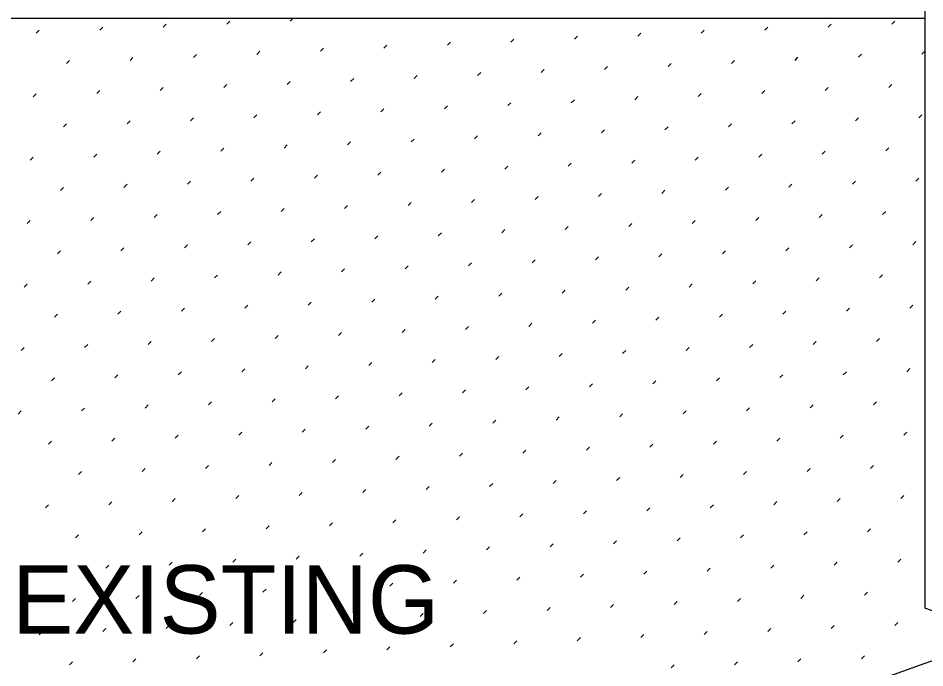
# Model space of a CAD drawing. Extents: x 49991.4 to 50021, y 49987.6 to 50011.4.
# Drawn here: x 50014.07 to 50015.13, y 49997.03 to 49997.79 of the extents above; entities that cross this region are included whole.
import ezdxf

# ---------------------------------------------------------------- set-up
doc = ezdxf.new("R2010")
doc.units = 0
for name, color, linetype in [('Level 1', 7, 'Continuous'), ('Level 10', 7, 'Continuous'), ('Level 2', 7, 'Continuous'), ('Level 6', 7, 'Continuous')]:
    doc.layers.add(name, color=color, linetype=linetype)

msp = doc.modelspace()

# ---------------------------------------------------------------- linework, layer by layer
at = {"layer": 'Level 1'}
msp.add_line((50011.6848, 49997.7903), (50015.1301, 49997.7903), dxfattribs=at)
at = {"layer": 'Level 10'}
for p, q in [((50014.2393, 49997.7797), (50014.2428, 49997.7833)), ((50014.3136, 49997.7833), (50014.3171, 49997.7868)), ((50014.3878, 49997.7868), (50014.3913, 49997.7904)), ((50015.0172, 49997.7798), (50015.0207, 49997.7834)), ((50015.0914, 49997.7834), (50015.095, 49997.7869)), ((50014.0908, 49997.7727), (50014.0943, 49997.7762)), ((50014.165, 49997.7762), (50014.1686, 49997.7797)), ((50014.7944, 49997.7692), (50014.798, 49997.7727)), ((50014.8687, 49997.7727), (50014.8722, 49997.7763)), ((50014.9429, 49997.7763), (50014.9465, 49997.7798)), ((50014.5717, 49997.7586), (50014.5752, 49997.7621)), ((50014.6459, 49997.7621), (50014.6495, 49997.7656)), ((50014.7202, 49997.7656), (50014.7237, 49997.7692)), ((50014.3489, 49997.7479), (50014.3524, 49997.7515)), ((50014.4232, 49997.7515), (50014.4267, 49997.755)), ((50014.4974, 49997.755), (50014.501, 49997.7586)), ((50015.1268, 49997.748), (50015.1303, 49997.7515)), ((50014.1262, 49997.7373), (50014.1297, 49997.7408)), ((50014.2004, 49997.7409), (50014.2039, 49997.7444)), ((50014.2747, 49997.7444), (50014.2782, 49997.7479)), ((50014.904, 49997.7374), (50014.9076, 49997.7409)), ((50014.9783, 49997.7409), (50014.9818, 49997.7445)), ((50015.0525, 49997.7445), (50015.0561, 49997.748)), ((50014.6813, 49997.7268), (50014.6848, 49997.7303)), ((50014.7555, 49997.7303), (50014.7591, 49997.7338)), ((50014.8298, 49997.7338), (50014.8333, 49997.7374)), ((50014.4585, 49997.7161), (50014.4621, 49997.7197)), ((50014.5328, 49997.7197), (50014.5363, 49997.7232)), ((50014.607, 49997.7232), (50014.6106, 49997.7267)), ((50014.2358, 49997.7055), (50014.2393, 49997.709)), ((50014.31, 49997.709), (50014.3135, 49997.7126)), ((50014.3843, 49997.7126), (50014.3878, 49997.7161)), ((50015.0136, 49997.7056), (50015.0172, 49997.7091)), ((50015.0879, 49997.7091), (50015.0914, 49997.7126)), ((50014.0873, 49997.6984), (50014.0908, 49997.7019)), ((50014.1615, 49997.702), (50014.165, 49997.7055)), ((50014.7909, 49997.6949), (50014.7944, 49997.6985)), ((50014.8651, 49997.6985), (50014.8687, 49997.702)), ((50014.9394, 49997.702), (50014.9429, 49997.7056)), ((50014.5681, 49997.6843), (50014.5717, 49997.6878)), ((50014.6424, 49997.6879), (50014.6459, 49997.6914)), ((50014.7166, 49997.6914), (50014.7202, 49997.6949)), ((50014.3454, 49997.6737), (50014.3489, 49997.6772)), ((50014.4196, 49997.6772), (50014.4232, 49997.6808)), ((50014.4939, 49997.6808), (50014.4974, 49997.6843)), ((50015.1233, 49997.6738), (50015.1268, 49997.6773)), ((50014.1226, 49997.6631), (50014.1261, 49997.6666)), ((50014.1969, 49997.6666), (50014.2004, 49997.6701)), ((50014.2711, 49997.6701), (50014.2747, 49997.6737)), ((50014.9005, 49997.6631), (50014.904, 49997.6667)), ((50014.9747, 49997.6667), (50014.9783, 49997.6702)), ((50015.049, 49997.6702), (50015.0525, 49997.6737)), ((50014.6777, 49997.6525), (50014.6813, 49997.656)), ((50014.752, 49997.656), (50014.7555, 49997.6596)), ((50014.8262, 49997.6596), (50014.8298, 49997.6631)), ((50014.455, 49997.6419), (50014.4585, 49997.6454)), ((50014.5292, 49997.6454), (50014.5328, 49997.6489)), ((50014.6035, 49997.649), (50014.607, 49997.6525)), ((50014.2322, 49997.6312), (50014.2358, 49997.6348)), ((50014.3065, 49997.6348), (50014.31, 49997.6383)), ((50014.3807, 49997.6383), (50014.3843, 49997.6419)), ((50015.0101, 49997.6313), (50015.0136, 49997.6348)), ((50015.0844, 49997.6349), (50015.0879, 49997.6384)), ((50014.0837, 49997.6242), (50014.0872, 49997.6277)), ((50014.158, 49997.6277), (50014.1615, 49997.6312)), ((50014.7873, 49997.6207), (50014.7909, 49997.6242)), ((50014.8616, 49997.6242), (50014.8651, 49997.6278)), ((50014.9359, 49997.6278), (50014.9394, 49997.6313)), ((50014.5646, 49997.6101), (50014.5681, 49997.6136)), ((50014.6388, 49997.6136), (50014.6424, 49997.6171)), ((50014.7131, 49997.6171), (50014.7166, 49997.6207)), ((50014.3418, 49997.5994), (50014.3454, 49997.603)), ((50014.4161, 49997.603), (50014.4196, 49997.6065)), ((50014.4903, 49997.6065), (50014.4939, 49997.6101)), ((50015.1197, 49997.5995), (50015.1232, 49997.603)), ((50014.1191, 49997.5888), (50014.1226, 49997.5923)), ((50014.1933, 49997.5923), (50014.1969, 49997.5959)), ((50014.2676, 49997.5959), (50014.2711, 49997.5994)), ((50014.897, 49997.5889), (50014.9005, 49997.5924)), ((50014.9712, 49997.5924), (50014.9747, 49997.596)), ((50015.0455, 49997.596), (50015.049, 49997.5995)), ((50014.6742, 49997.5782), (50014.6777, 49997.5818)), ((50014.7484, 49997.5818), (50014.752, 49997.5853)), ((50014.8227, 49997.5853), (50014.8262, 49997.5889)), ((50014.4514, 49997.5676), (50014.455, 49997.5712)), ((50014.5257, 49997.5712), (50014.5292, 49997.5747)), ((50014.5999, 49997.5747), (50014.6035, 49997.5782)), ((50014.2287, 49997.557), (50014.2322, 49997.5605)), ((50014.3029, 49997.5605), (50014.3065, 49997.5641)), ((50014.3772, 49997.5641), (50014.3807, 49997.5676)), ((50015.0066, 49997.5571), (50015.0101, 49997.5606)), ((50015.0808, 49997.5606), (50015.0844, 49997.5641)), ((50014.0802, 49997.5499), (50014.0837, 49997.5534)), ((50014.1544, 49997.5534), (50014.158, 49997.557)), ((50014.7838, 49997.5464), (50014.7873, 49997.55)), ((50014.8581, 49997.55), (50014.8616, 49997.5535)), ((50014.9323, 49997.5535), (50014.9358, 49997.5571)), ((50014.561, 49997.5358), (50014.5646, 49997.5393)), ((50014.6353, 49997.5393), (50014.6388, 49997.5429)), ((50014.7095, 49997.5429), (50014.7131, 49997.5464)), ((50014.3383, 49997.5252), (50014.3418, 49997.5287)), ((50014.4125, 49997.5287), (50014.4161, 49997.5323)), ((50014.4868, 49997.5323), (50014.4903, 49997.5358)), ((50015.1162, 49997.5252), (50015.1197, 49997.5288)), ((50014.1155, 49997.5145), (50014.1191, 49997.5181)), ((50014.1898, 49997.5181), (50014.1933, 49997.5216)), ((50014.264, 49997.5216), (50014.2676, 49997.5252)), ((50014.8934, 49997.5146), (50014.8969, 49997.5182)), ((50014.9677, 49997.5182), (50014.9712, 49997.5217)), ((50015.0419, 49997.5217), (50015.0455, 49997.5252)), ((50014.6707, 49997.504), (50014.6742, 49997.5075)), ((50014.7449, 49997.5075), (50014.7484, 49997.5111)), ((50014.8192, 49997.5111), (50014.8227, 49997.5146)), ((50014.4479, 49997.4934), (50014.4514, 49997.4969)), ((50014.5221, 49997.4969), (50014.5257, 49997.5004)), ((50014.5964, 49997.5004), (50014.5999, 49997.504)), ((50014.2251, 49997.4827), (50014.2287, 49997.4863)), ((50014.2994, 49997.4863), (50014.3029, 49997.4898)), ((50014.3736, 49997.4898), (50014.3772, 49997.4934)), ((50015.003, 49997.4828), (50015.0066, 49997.4863)), ((50015.0773, 49997.4863), (50015.0808, 49997.4899)), ((50014.0766, 49997.4757), (50014.0802, 49997.4792)), ((50014.1509, 49997.4792), (50014.1544, 49997.4827)), ((50014.7803, 49997.4722), (50014.7838, 49997.4757)), ((50014.8545, 49997.4757), (50014.858, 49997.4793)), ((50014.9288, 49997.4793), (50014.9323, 49997.4828)), ((50014.5575, 49997.4616), (50014.561, 49997.4651)), ((50014.6318, 49997.4651), (50014.6353, 49997.4686)), ((50014.706, 49997.4686), (50014.7095, 49997.4722)), ((50014.3347, 49997.4509), (50014.3383, 49997.4545)), ((50014.409, 49997.4545), (50014.4125, 49997.458)), ((50014.4832, 49997.458), (50014.4868, 49997.4615)), ((50015.1126, 49997.451), (50015.1162, 49997.4545)), ((50014.112, 49997.4403), (50014.1155, 49997.4438)), ((50014.1862, 49997.4438), (50014.1898, 49997.4474)), ((50014.2605, 49997.4474), (50014.264, 49997.4509)), ((50014.8899, 49997.4404), (50014.8934, 49997.4439)), ((50014.9641, 49997.4439), (50014.9677, 49997.4474)), ((50015.0384, 49997.4475), (50015.0419, 49997.451)), ((50014.6671, 49997.4297), (50014.6706, 49997.4333)), ((50014.7414, 49997.4333), (50014.7449, 49997.4368)), ((50014.8156, 49997.4368), (50014.8192, 49997.4404)), ((50014.4443, 49997.4191), (50014.4479, 49997.4226)), ((50014.5186, 49997.4227), (50014.5221, 49997.4262)), ((50014.5929, 49997.4262), (50014.5964, 49997.4297)), ((50014.2216, 49997.4085), (50014.2251, 49997.412)), ((50014.2958, 49997.412), (50014.2994, 49997.4156)), ((50014.3701, 49997.4156), (50014.3736, 49997.4191)), ((50014.9995, 49997.4086), (50015.003, 49997.4121)), ((50015.0737, 49997.4121), (50015.0773, 49997.4156)), ((50014.0731, 49997.4014), (50014.0766, 49997.4049)), ((50014.1473, 49997.4049), (50014.1509, 49997.4085)), ((50014.7767, 49997.3979), (50014.7803, 49997.4015)), ((50014.851, 49997.4015), (50014.8545, 49997.405)), ((50014.9252, 49997.405), (50014.9288, 49997.4085)), ((50014.554, 49997.3873), (50014.5575, 49997.3908)), ((50014.6282, 49997.3908), (50014.6317, 49997.3944)), ((50014.7025, 49997.3944), (50014.706, 49997.3979)), ((50014.3312, 49997.3767), (50014.3347, 49997.3802)), ((50014.4055, 49997.3802), (50014.409, 49997.3837)), ((50014.4797, 49997.3838), (50014.4832, 49997.3873)), ((50015.1091, 49997.3767), (50015.1126, 49997.3803)), ((50014.1084, 49997.366), (50014.112, 49997.3696)), ((50014.1827, 49997.3696), (50014.1862, 49997.3731)), ((50014.2569, 49997.3731), (50014.2605, 49997.3767)), ((50014.8863, 49997.3661), (50014.8899, 49997.3696)), ((50014.9606, 49997.3697), (50014.9641, 49997.3732)), ((50015.0348, 49997.3732), (50015.0384, 49997.3767)), ((50014.6636, 49997.3555), (50014.6671, 49997.359)), ((50014.7378, 49997.359), (50014.7414, 49997.3626)), ((50014.8121, 49997.3626), (50014.8156, 49997.3661)), ((50014.4408, 49997.3449), (50014.4443, 49997.3484)), ((50014.5151, 49997.3484), (50014.5186, 49997.3519)), ((50014.5893, 49997.3519), (50014.5928, 49997.3555)), ((50014.218, 49997.3342), (50014.2216, 49997.3378)), ((50014.2923, 49997.3378), (50014.2958, 49997.3413)), ((50014.3666, 49997.3413), (50014.3701, 49997.3449)), ((50014.9959, 49997.3343), (50014.9995, 49997.3378)), ((50015.0702, 49997.3378), (50015.0737, 49997.3414)), ((50014.0695, 49997.3271), (50014.0731, 49997.3307)), ((50014.1438, 49997.3307), (50014.1473, 49997.3342)), ((50014.7732, 49997.3237), (50014.7767, 49997.3272)), ((50014.8474, 49997.3272), (50014.851, 49997.3308)), ((50014.9217, 49997.3308), (50014.9252, 49997.3343)), ((50014.5504, 49997.313), (50014.554, 49997.3166)), ((50014.6247, 49997.3166), (50014.6282, 49997.3201)), ((50014.6989, 49997.3201), (50014.7025, 49997.3237)), ((50014.3277, 49997.3024), (50014.3312, 49997.306)), ((50014.4019, 49997.306), (50014.4054, 49997.3095)), ((50014.4762, 49997.3095), (50014.4797, 49997.313)), ((50015.1055, 49997.3025), (50015.1091, 49997.306)), ((50014.1049, 49997.2918), (50014.1084, 49997.2953)), ((50014.1791, 49997.2953), (50014.1827, 49997.2989)), ((50014.2534, 49997.2989), (50014.2569, 49997.3024)), ((50014.8828, 49997.2919), (50014.8863, 49997.2954)), ((50014.957, 49997.2954), (50014.9606, 49997.2989)), ((50015.0313, 49997.2989), (50015.0348, 49997.3025)), ((50014.66, 49997.2812), (50014.6636, 49997.2848)), ((50014.7343, 49997.2848), (50014.7378, 49997.2883)), ((50014.8085, 49997.2883), (50014.8121, 49997.2919)), ((50014.4373, 49997.2706), (50014.4408, 49997.2741)), ((50014.5115, 49997.2741), (50014.5151, 49997.2777)), ((50014.5858, 49997.2777), (50014.5893, 49997.2812)), ((50014.2145, 49997.26), (50014.218, 49997.2635)), ((50014.2888, 49997.2635), (50014.2923, 49997.2671)), ((50014.363, 49997.2671), (50014.3665, 49997.2706)), ((50014.9924, 49997.26), (50014.9959, 49997.2636)), ((50015.0666, 49997.2636), (50015.0702, 49997.2671)), ((50014.1403, 49997.2564), (50014.1438, 49997.26)), ((50014.7696, 49997.2494), (50014.7732, 49997.253)), ((50014.8439, 49997.253), (50014.8474, 49997.2565)), ((50014.9181, 49997.2565), (50014.9217, 49997.26)), ((50014.5469, 49997.2388), (50014.5504, 49997.2423)), ((50014.6211, 49997.2423), (50014.6247, 49997.2459)), ((50014.6954, 49997.2459), (50014.6989, 49997.2494)), ((50014.3241, 49997.2282), (50014.3276, 49997.2317)), ((50014.3984, 49997.2317), (50014.4019, 49997.2352)), ((50014.4726, 49997.2352), (50014.4762, 49997.2388)), ((50015.102, 49997.2282), (50015.1055, 49997.2318)), ((50014.1014, 49997.2175), (50014.1049, 49997.2211)), ((50014.1756, 49997.2211), (50014.1791, 49997.2246)), ((50014.2499, 49997.2246), (50014.2534, 49997.2282)), ((50014.8792, 49997.2176), (50014.8828, 49997.2211)), ((50014.9535, 49997.2211), (50014.957, 49997.2247)), ((50015.0277, 49997.2247), (50015.0313, 49997.2282)), ((50014.6565, 49997.207), (50014.66, 49997.2105)), ((50014.7307, 49997.2105), (50014.7343, 49997.2141)), ((50014.805, 49997.2141), (50014.8085, 49997.2176)), ((50014.4337, 49997.1964), (50014.4373, 49997.1999)), ((50014.508, 49997.1999), (50014.5115, 49997.2034)), ((50014.5822, 49997.2034), (50014.5858, 49997.207)), ((50014.211, 49997.1857), (50014.2145, 49997.1893)), ((50014.2852, 49997.1893), (50014.2888, 49997.1928)), ((50014.3595, 49997.1928), (50014.363, 49997.1963)), ((50014.9888, 49997.1858), (50014.9924, 49997.1893)), ((50015.0631, 49997.1893), (50015.0666, 49997.1929)), ((50014.1367, 49997.1822), (50014.1402, 49997.1857)), ((50014.7661, 49997.1752), (50014.7696, 49997.1787)), ((50014.8403, 49997.1787), (50014.8439, 49997.1822)), ((50014.9146, 49997.1823), (50014.9181, 49997.1858)), ((50014.5433, 49997.1645), (50014.5469, 49997.1681)), ((50014.6176, 49997.1681), (50014.6211, 49997.1716)), ((50014.6918, 49997.1716), (50014.6954, 49997.1752)), ((50014.3206, 49997.1539), (50014.3241, 49997.1574)), ((50014.3948, 49997.1575), (50014.3984, 49997.161)), ((50014.4691, 49997.161), (50014.4726, 49997.1645)), ((50015.0985, 49997.154), (50015.102, 49997.1575)), ((50014.0978, 49997.1433), (50014.1013, 49997.1468)), ((50014.1721, 49997.1468), (50014.1756, 49997.1504)), ((50014.2463, 49997.1504), (50014.2499, 49997.1539)), ((50014.8757, 49997.1434), (50014.8792, 49997.1469)), ((50014.95, 49997.1469), (50014.9535, 49997.1504)), ((50015.0242, 49997.1504), (50015.0277, 49997.154)), ((50014.6529, 49997.1327), (50014.6565, 49997.1363)), ((50014.7272, 49997.1363), (50014.7307, 49997.1398)), ((50014.8014, 49997.1398), (50014.805, 49997.1433)), ((50014.4302, 49997.1221), (50014.4337, 49997.1256)), ((50014.5044, 49997.1256), (50014.508, 49997.1292)), ((50014.5787, 49997.1292), (50014.5822, 49997.1327)), ((50014.2074, 49997.1115), (50014.211, 49997.115)), ((50014.2817, 49997.115), (50014.2852, 49997.1185)), ((50014.3559, 49997.1186), (50014.3595, 49997.1221)), ((50014.9853, 49997.1115), (50014.9888, 49997.1151)), ((50015.0596, 49997.1151), (50015.0631, 49997.1186)), ((50014.1332, 49997.1079), (50014.1367, 49997.1115)), ((50014.7625, 49997.1009), (50014.7661, 49997.1044)), ((50014.8368, 49997.1045), (50014.8403, 49997.108)), ((50014.9111, 49997.108), (50014.9146, 49997.1115)), ((50014.5398, 49997.0903), (50014.5433, 49997.0938)), ((50014.614, 49997.0938), (50014.6176, 49997.0974)), ((50014.6883, 49997.0974), (50014.6918, 49997.1009)), ((50014.317, 49997.0797), (50014.3206, 49997.0832)), ((50014.3913, 49997.0832), (50014.3948, 49997.0867)), ((50014.4655, 49997.0867), (50014.4691, 49997.0903)), ((50015.0949, 49997.0797), (50015.0985, 49997.0833)), ((50014.0943, 49997.069), (50014.0978, 49997.0726)), ((50014.1685, 49997.0726), (50014.1721, 49997.0761)), ((50014.2428, 49997.0761), (50014.2463, 49997.0796)), ((50014.8722, 49997.0691), (50014.8757, 49997.0726)), ((50014.9464, 49997.0726), (50014.9499, 49997.0762)), ((50015.0207, 49997.0762), (50015.0242, 49997.0797)), ((50014.6494, 49997.0585), (50014.6529, 49997.062)), ((50014.7236, 49997.062), (50014.7272, 49997.0656)), ((50014.7979, 49997.0656), (50014.8014, 49997.0691)), ((50014.4266, 49997.0478), (50014.4302, 49997.0514)), ((50014.5009, 49997.0514), (50014.5044, 49997.0549)), ((50014.5751, 49997.0549), (50014.5787, 49997.0585)), ((50014.2039, 49997.0372), (50014.2074, 49997.0408)), ((50014.2781, 49997.0408), (50014.2817, 49997.0443)), ((50014.3524, 49997.0443), (50014.3559, 49997.0478)), ((50014.9818, 49997.0373), (50014.9853, 49997.0408)), ((50015.056, 49997.0408), (50015.0596, 49997.0444)), ((50014.1296, 49997.0337), (50014.1332, 49997.0372)), ((50014.8333, 49997.0302), (50014.8368, 49997.0337)), ((50014.9075, 49997.0337), (50014.911, 49997.0373))]:
    msp.add_line(p, q, dxfattribs=at)
at = {"layer": 'Level 6'}
for p, q in [((50015.1301, 49998.3903), (50015.1301, 49997.1)), ((50015.2215, 49997.0676), (50015.1301, 49997.1)), ((50015.2215, 49997.0676), (50015.1301, 49997.0352)), ((50015.1301, 49997.0352), (50015.0387, 49997.0028))]:
    msp.add_line(p, q, dxfattribs=at)

# ---------------------------------------------------------------- texts
at = {"layer": 'Level 2'}
msp.add_text('EXISTING', height=0.08, dxfattribs=at).set_placement((50014.0626, 49997.0703))

doc.saveas('drawing.dxf')
